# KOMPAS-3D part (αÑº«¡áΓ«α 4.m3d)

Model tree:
1. Эскиз:1
2. Операция выдавливания:1
     Толщина стенки 1 = 2; Толщина стенки 2 = 8; Расстояние 1 = 1
3. Эскиз:3
4. Операция выдавливания:2
     Толщина стенки 1 = 2; Толщина стенки 2 = 6; Расстояние 1 = 5
5. Эскиз:4
6. Операция выдавливания:3
     Толщина стенки 1 = 2; Толщина стенки 2 = 6; Расстояние 1 = 1
7. Эскиз:5
8. Эскиз:6
9. Операция выдавливания:4
     Толщина стенки 1 = 2; Толщина стенки 2 = 2.5; Расстояние 1 = 50
10. Эскиз:7
11. Вырезать элемент выдавливания:1
     Толщина стенки 2 = 1.5; Расстояние 1 = 40
12. Эскиз:8
13. Операция выдавливания:5
     Толщина стенки 1 = 2; Толщина стенки 2 = 2.5; Расстояние 1 = 50
14. Эскиз:9
15. Вырезать элемент выдавливания:2
     Толщина стенки 2 = 1.5; Расстояние 1 = 40
16. Эскиз:10
17. Операция выдавливания:6
     Толщина стенки 1 = 2; Толщина стенки 2 = 2.5; Расстояние 1 = 10
18. Эскиз:11
19. Операция выдавливания:7
     Толщина стенки 1 = 2; Толщина стенки 2 = 6; Расстояние 1 = 1
20. Эскиз:12
21. Операция выдавливания:8
     Толщина стенки 1 = 2; Толщина стенки 2 = 6; Расстояние 1 = 5
22. Эскиз:13
23. Операция выдавливания:9
     Толщина стенки 1 = 2; Толщина стенки 2 = 8; Расстояние 1 = 1
24. Эскиз:14
25. Вырезать элемент выдавливания:3
     Толщина стенки 2 = 1.5; Расстояние 1 = 23
26. Эскиз:15
27. Вырезать элемент выдавливания:4
     Толщина стенки 2 = 1.5; Расстояние 1 = 1
28. Эскиз:16
29. Вырезать элемент выдавливания:5
     Расстояние 1 = 150
30. Эскиз:19
31. Операция выдавливания:12
     Толщина стенки 1 = 7; Расстояние 1 = 10; Расстояние 2 = 0.4
